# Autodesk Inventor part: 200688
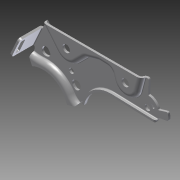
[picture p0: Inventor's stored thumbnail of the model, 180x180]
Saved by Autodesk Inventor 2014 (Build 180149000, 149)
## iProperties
Created: 2007-11
Part Number: 200688
Document SubType Name: Modeling
Designer: TH
Density: 7.85 g/cm^3
Mass: 313.071 g
Surface Area: 247.504 cm^2
Volume: 39.8817 cm^3
Material: Steel
Description: BACK SUPPORT PLATE
Appearance: Steel
Component Category: Lower Component
Author: TH
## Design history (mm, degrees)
sketch "Sketch2"
  geometry: L1 (-97.344, 50.026)-(-159.459, 48.117); L2 (-34.744, 9.425)-(-45.417, 12.32); L3 (-45.417, 12.32)-(-51.753, 20.365); L4 (-51.753, 20.365)-(-57.155, 19.109); L5 (4.666, 94.599)-(-151.434, 94.599); L6 (22.488, 55.351)-(4.666, 94.599); L7 (22.488, 55.351)-(17.318, 53.004); L8 (17.318, 53.004)-(19.939, 41.738); L9 (19.939, 41.738)-(15.518, 32.484); A1 r 36 centre (0, 0) between (15.518, 32.484) and (-34.744, 9.425); A2 r 40 centre (-96.115, 10.045) between (-57.155, 19.109) and (-97.344, 50.026); A3 r 24.073 centre (-160.199, 72.178) between (-151.434, 94.599) and (-159.459, 48.117); 1 further point
  constraints: 18 end point, 6 point on circle, 4 point on line, 3 centre point, 2 perpendicular, 2 tangent, 1 coincident
  dimensions: "d0" = 36 radius of A1; "d1" = 24.07258 radius of A3; "d2" = 40 radius of A2; "d3" = 94.59889 distance from line of point (0, 0) L5; "d4" = 160.19856 horizontal distance of point (0, 0) A3.centre; "d5" = 72.17844 vertical distance of point (0, 0) A3.centre; "d6" = 96.11496 horizontal distance of point (0, 0) A2.centre; "d7" = 10.04515 vertical distance of A2.centre point (0, 0); "d9" = 12.31989 vertical distance of point (0, 0) L2.end; "d10" = 20.36546 vertical distance of point (0, 0) L3.end; "d11" = 19.10873 vertical distance of point (0, 0) L4.end; "d12" = 45.41698 horizontal distance of point (0, 0) L2.end; "d15" = 19.9388 horizontal distance of point (0, 0) L8.end; "d16" = 17.31793 horizontal distance of point (0, 0) L7.end; "d17" = 55.35127 vertical distance of point (0, 0) L6.start; "d18" = 22.48806 horizontal distance of point (0, 0) L6.start; "d19" = 151.43427 horizontal distance of L5.end point (0, 0); "d137" = 41.73777 vertical distance of point (0, 0) L8.end
extrude "Extrusion1" new body sketch "Sketch2" distance "d20" = 3; taper "d21" = 0 deg
fillet "Fillet1" dims "d22" = 25
fillet "Fillet2" dims "d23" = 2
fillet "Fillet3" dims "d24" = 4
sketch "Sketch3"
  geometry: L1 (-4.666, -94.599)-(147.572, -94.599) reference; L2 (159.459, -48.117)-(97.344, -50.026) reference; L3 (45.417, -12.32)-(34.744, -9.425) reference; L4 (0, 23.92)-(0, -143.519) reference; L5 (228.741, 0)-(-64.359, 0) reference; L6 (0, -94.599)-(21.365, -68.832); L7 (99.254, -87.507)-(80, -88.099); L8 (80, -88.099)-(60, -82.674); L9 (60, -82.674)-(44.972, -67.708); L10 (99.254, -87.507)-(103.61, -74.101); L11 (139.559, -94.599)-(134.282, -74.904); A1 r 25 centre (147.572, -119.599) between (154.005, -95.441) and (147.572, -94.599) reference; A2 r 24.073 centre (160.199, -72.178) between (154.005, -95.441) and (159.459, -48.117) reference; A3 r 36 centre (0, 0) between (-15.518, -32.484) and (34.744, -9.425) reference; A4 r 16 centre (33.682, -79.045) between (21.365, -68.832) and (44.972, -67.708); A5 r 16 centre (118.827, -79.045) between (103.61, -74.101) and (134.282, -74.904)
  constraints: 12 end point, 4 point on circle, 4 tangent, 3 point on line, 2 centre point, 2 parallel
  dimensions: "d25" = 79.04516 vertical distance of A3.centre A4.centre; "d26" = 33.68204 horizontal distance of A3.centre A4.centre; "d28" = 79.04516 vertical distance of A3.centre A5.centre; "d29" = 32 diameter of A4; "d30" = 32 diameter of A5; "d33" = 60 distance from line of L8.end L4; "d34" = 80 distance from line of L4 L7.end; "d55" = 6.5 distance from line of L1 L7.end; "d170" = 118.82692 distance from line of A5.centre L4; "d171" = 15 deg angle of L11 L4; "d172" = 33 deg angle of L11 L10
extrude "Extrusion2" cut sketch "Sketch3" distance "d36" = 5; taper "d37" = 0 deg
fillet "Fillet4" dims "d38" = 10
sketch "Sketch4"
  geometry: L1 (53, -11.358)-(53, 0); L2 (53, 0)-(0, 0); L3 (53, 0)-(-52.769, 0); L4 (-52.769, 0)-(-27.664, -46.955); A1 r 36 centre (0, 0) between (-15.518, -32.484) and (34.744, -9.425) reference; A2 r 24 centre (57.131, -35) between (53, -11.358) and (36.666, -22.463); A3 r 47.5 centre (-7.912, -90.153) between (-3.759, -42.835) and (-27.664, -46.955); A4 r 43 centre (0, 0) between (-3.759, -42.835) and (36.666, -22.463)
  constraints: 8 end point, 6 point on circle, 3 centre point, 2 tangent, 1 coincident, 1 collinear, 1 horizontal, 1 perpendicular
  dimensions: "d42" = 24 radius of A2; "d43" = 95 diameter of A3; "d45" = 52.76853 distance of L3.end A1.centre; "d46" = 43 radius of A4; "d47" = 27.66425 horizontal distance of A1.centre L4.end; "d48" = 61.869 deg angle of L3 L4; "d138" = 35 distance from line of L3 A2.centre; "d139" = 53 distance from line of A1.centre L1
extrude "Extrusion3" cut sketch "Sketch4" distance "d51" = 5; taper "d52" = 0 deg
sketch "Sketch9"
  geometry: L1 (45.417, 12.32)-(51.753, 20.365) reference; L2 (34.744, 9.425)-(45.417, 12.32) reference; L3 (-19.939, 41.738)-(-15.518, 32.484) reference; L4 (-17.318, 53.004)-(-19.939, 41.738) reference; L5 (48.281, 15.956)-(46.38, 13.543); A1 r 24 centre (57.131, 35) between (36.666, 22.463) and (46.38, 13.543) reference; A2 r 47.5 centre (-7.912, 90.153) between (-19.398, 44.063) and (-3.759, 42.835) reference; A3 r 43 centre (0, 0) between (36.666, 22.463) and (-3.759, 42.835) reference; A4 r 36 centre (0, 0) between (34.744, 9.425) and (-15.518, 32.484) reference; A5 r 44.5 centre (-7.912, 90.153) between (-18.718, 46.985) and (-4.022, 45.824); A6 r 46 centre (0, 0) between (39.225, 24.03) and (-4.022, 45.824); A7 r 21 centre (57.131, 35) between (39.225, 24.03) and (48.281, 15.956)
  constraints: 6 point on circle, 3 centre point, 2 end point, 2 point on line, 1 collinear
  dimensions: "d73" = 3 radial gap between concentric circles of A3 A6; "d74" = 21 radius of A7; "d75" = 44.5 radius of A5
extrude "Extrusion7" join sketch "Sketch9" distance "d76" = 3; taper "d77" = 0 deg
sketch "Sketch10"
  geometry: L1 (48.281, 15.956)-(46.38, 13.543) reference; L2 (-19.398, 44.063)-(-18.718, 46.985) reference; L3 (34.744, 9.425)-(45.417, 12.32) reference; L4 (-19.939, 41.738)-(-15.518, 32.484) reference; L5 (46.38, 13.543)-(45.417, 12.32); L6 (-19.939, 41.738)-(-19.398, 44.063); A1 r 43 centre (0, 0) between (36.666, 22.463) and (-3.759, 42.835) reference; A2 r 24 centre (57.131, 35) between (36.666, 22.463) and (46.38, 13.543) reference; A3 r 21 centre (57.131, 35) between (39.225, 24.03) and (48.281, 15.956) reference; A4 r 46 centre (0, 0) between (39.225, 24.03) and (-4.022, 45.824) reference; A5 r 44.5 centre (-7.912, 90.153) between (-18.718, 46.985) and (-4.022, 45.824) reference; A6 r 47.5 centre (-7.912, 90.153) between (-19.398, 44.063) and (-3.759, 42.835) reference; A7 r 36 centre (0, 0) between (34.744, 9.425) and (-15.518, 32.484) reference
  constraints: 4 end point, 2 collinear
extrude "Extrusion8" join sketch "Sketch10" distance "d78" = 3; taper "d79" = 0 deg
fillet "Fillet11" dims "d80" = 4
fillet "Fillet12" dims "d81" = 7
fillet "Fillet13" dims "d82" = 1
sketch "Sketch11"
  geometry: L1 (50.18, 18.368)-(48.801, 16.617) reference; L2 (57.155, 19.109)-(54.229, 19.789) reference; L3 (159.459, 48.117)-(97.344, 50.026) reference; L4 (103.61, 74.101)-(101.427, 80.818) reference; L5 (92.224, 87.723)-(81.488, 88.053) reference; L6 (78.563, 87.709)-(62.559, 83.368) reference; L7 (58.121, 80.802)-(44.972, 67.708) reference; L8 (21.365, 68.832)-(0, 94.599) reference; L9 (-4.666, 94.599)-(0, 94.599) reference; L10 (-22.488, 55.351)-(-4.666, 94.599) reference; L11 (-18.81, 53.681)-(-22.488, 55.351) reference; L12 (-18.533, 47.782)-(-17.689, 51.407) reference; L13 (49.718, 18.733)-(48.628, 17.348); L14 (-17.827, 48.216)-(-17.116, 51.274); L15 (-18.567, 54.217)-(-21.708, 55.644); L16 (-21.708, 55.644)-(-4.287, 94.01); L17 (-4.287, 94.01)-(-0.277, 94.01); L18 (-0.277, 94.01)-(20.912, 68.456); L19 (45.388, 67.291)-(58.536, 80.385); L20 (62.714, 82.8)-(78.717, 87.141); L21 (81.47, 87.465)-(92.206, 87.135); L22 (100.867, 80.636)-(103.05, 73.919); L23 (134.851, 74.752)-(140.035, 94.101); L24 (159.551, 51.116)-(97.436, 53.025); L25 (159.551, 51.116)-(159.459, 48.117); A1 r 43.682 centre (-7.912, 90.153) between (-18.533, 47.782) and (-4.093, 46.638) reference; A2 r 46.818 centre (0, 0) between (39.922, 24.457) and (-4.093, 46.638) reference; A3 r 20.182 centre (57.131, 35) between (39.922, 24.457) and (48.801, 16.617) reference; A4 r 40 centre (96.115, 10.045) between (97.344, 50.026) and (57.155, 19.109) reference; A5 r 16 centre (118.827, 79.045) between (103.61, 74.101) and (134.282, 74.904) reference; A6 r 10 centre (91.917, 77.728) between (101.427, 80.818) and (92.224, 87.723) reference; A7 r 10 centre (81.181, 78.058) between (81.488, 88.053) and (78.563, 87.709) reference; A8 r 10 centre (65.177, 73.717) between (62.559, 83.368) and (58.121, 80.802) reference; A9 r 16 centre (33.682, 79.045) between (21.365, 68.832) and (44.972, 67.708) reference; A10 r 2 centre (-19.637, 51.86) between (-17.689, 51.407) and (-18.81, 53.681) reference; A11 r 19.593 centre (57.131, 35) between (40.424, 24.765) and (48.628, 17.348); A12 r 47.407 centre (0, 0) between (40.424, 24.765) and (-4.145, 47.225); A13 r 43.093 centre (-7.912, 90.153) between (-17.827, 48.216) and (-4.145, 47.225); A14 r 2.589 centre (-19.637, 51.86) between (-17.116, 51.274) and (-18.567, 54.217); A15 r 16.589 centre (33.682, 79.045) between (20.912, 68.456) and (45.388, 67.291); A16 r 9.411 centre (65.177, 73.717) between (62.714, 82.8) and (58.536, 80.385); A17 r 9.411 centre (81.181, 78.058) between (81.47, 87.465) and (78.717, 87.141); A18 r 9.411 centre (91.917, 77.728) between (100.867, 80.636) and (92.206, 87.135); A19 r 16.589 centre (118.827, 79.045) between (103.05, 73.919) and (134.851, 74.752); A20 r 43 centre (96.115, 10.045) between (97.436, 53.025) and (54.233, 19.789); 2 further points; 1 other entity
  constraints: 26 end point, 20 point on circle, 10 centre point, 1 perpendicular, 1 point on line, 20 other
  dimensions: "d83" = 3 distance between parallel lines of L3 L24; "d84" = 43 radius of A20
extrude "Extrusion9" join sketch "Sketch11" distance "d85" = 4; taper "d86" = 0 deg
sketch "Sketch12"
  geometry: L1 (103.61, 74.101)-(101.427, 80.818) reference; L2 (92.224, 87.723)-(81.488, 88.053) reference; L3 (78.563, 87.709)-(62.559, 83.368) reference; L4 (58.121, 80.802)-(44.972, 67.708) reference; L5 (21.365, 68.832)-(0, 94.599) reference; L6 (-1.41, 91.599)-(19.056, 66.917); L7 (47.089, 65.582)-(60.238, 78.677); L8 (63.345, 80.473)-(79.348, 84.814); L9 (81.396, 85.055)-(92.132, 84.725); L10 (98.574, 79.891)-(100.757, 73.174); L11 (137.18, 74.128)-(142.665, 94.599); L12 (-1.41, 91.599)-(0, 94.599); L13 (139.559, 94.599)-(147.572, 94.599) reference; A1 r 16 centre (118.827, 79.045) between (103.61, 74.101) and (134.282, 74.904) reference; A2 r 10 centre (91.917, 77.728) between (101.427, 80.818) and (92.224, 87.723) reference; A3 r 10 centre (81.181, 78.058) between (81.488, 88.053) and (78.563, 87.709) reference; A4 r 10 centre (65.177, 73.717) between (62.559, 83.368) and (58.121, 80.802) reference; A5 r 16 centre (33.682, 79.045) between (21.365, 68.832) and (44.972, 67.708) reference; A6 r 19 centre (33.682, 79.045) between (19.056, 66.917) and (47.089, 65.582); A7 r 7 centre (65.177, 73.717) between (63.345, 80.473) and (60.238, 78.677); A8 r 7 centre (81.181, 78.058) between (81.396, 85.055) and (79.348, 84.814); A9 r 7 centre (91.917, 77.728) between (98.574, 79.891) and (92.132, 84.725); A10 r 19 centre (118.827, 79.045) between (100.757, 73.174) and (137.18, 74.128); A11 r 24.073 centre (160.199, 72.178) between (159.459, 48.117) and (154.005, 95.441) reference; 2 further points; 1 other entity
  constraints: 14 end point, 11 point on circle, 5 centre point, 2 point on line, 10 other
  dimensions: "d87" = 3 distance between parallel lines of L2 L9; "d88" = 3 dimension on L11
extrude "Extrusion10" join sketch "Sketch12" distance "d89" = 3; taper "d90" = 0 deg
sketch "Sketch13"
  geometry: L1 (101.427, 80.818)-(103.61, 74.101) reference; L2 (81.488, 88.053)-(92.224, 87.723) reference; L3 (62.559, 83.368)-(78.563, 87.709) reference; L4 (44.972, 67.708)-(58.121, 80.802) reference; L5 (0, 94.599)-(21.365, 68.832) reference; L6 (-1.41, 91.599)-(0, 94.599) reference; L7 (19.056, 66.917)-(-1.41, 91.599) reference; L8 (60.238, 78.677)-(47.089, 65.582) reference; L9 (79.348, 84.814)-(63.345, 80.473) reference; L10 (92.132, 84.725)-(81.396, 85.055) reference; L11 (100.757, 73.174)-(98.574, 79.891) reference; L12 (142.665, 94.599)-(137.18, 74.128) reference; L13 (0, 94.599)-(0, 94.599); L14 (0, 94.599)-(142.665, 94.599); A1 r 16 centre (118.827, 79.045) between (103.61, 74.101) and (134.282, 74.904) reference; A2 r 10 centre (91.917, 77.728) between (101.427, 80.818) and (92.224, 87.723) reference; A3 r 10 centre (81.181, 78.058) between (81.488, 88.053) and (78.563, 87.709) reference; A4 r 10 centre (65.177, 73.717) between (62.559, 83.368) and (58.121, 80.802) reference; A5 r 16 centre (33.682, 79.045) between (21.365, 68.832) and (44.972, 67.708) reference; A6 r 19 centre (33.682, 79.045) between (19.056, 66.917) and (47.089, 65.582) reference; A7 r 7 centre (65.177, 73.717) between (63.345, 80.473) and (60.238, 78.677) reference; A8 r 7 centre (81.181, 78.058) between (81.396, 85.055) and (79.348, 84.814) reference; A9 r 7 centre (91.917, 77.728) between (98.574, 79.891) and (92.132, 84.725) reference; A10 r 19 centre (118.827, 79.045) between (100.757, 73.174) and (137.18, 74.128) reference; A11 r 37.952 centre (160.199, 72.178) between (123.216, 63.659) and (124.004, 60.764); 2 further points
  constraints: 4 end point, 4 point on circle, 1 centre point, 1 collinear, 1 horizontal, 1 point on line
extrude "Extrusion11" join sketch "Sketch13" distance "d92" = 3; taper "d93" = 0 deg
fillet "Fillet14" dims "d94" = 4
fillet "Fillet15" dims "d95" = 7, "d96" = 1
fillet "Fillet16" dims "d97" = 4
fillet "Fillet18" dims "d99" = 2
sketch "Sketch14"
  geometry: L1 (159.459, -48.117)-(97.344, -50.026) reference; L2 (159.459, -48.117)-(159.459, -53.12); L3 (159.459, -53.12)-(178.13, -56.117); A1 r 24.073 centre (160.199, -72.178) between (154.005, -95.441) and (159.459, -48.117) reference; 2 further points
  constraints: 4 end point, 1 point on circle
  dimensions: "d100" = 0 horizontal distance of L1.start L2.end; "d101" = 5 distance from line of L2.end L1; "d102" = 8 vertical distance of L1.start L3.end
extrude "Extrusion12" cut sketch "Sketch14" stored distance "d103" = 3; taper "d104" = 0 deg
fillet "Fillet19" dims "d105" = 4
fillet "Fillet20" dims "d106" = 1
fillet "Fillet21" dims "d107" = 15
fillet "Fillet22" dims "d108" = 5
fillet "Fillet23" dims "d109" = 2.5
sketch "Sketch15"
  geometry: L1 (0, 0)-(30, 0); L2 (30, 0)-(30, -32); L3 (30, -32)-(0, -32); L4 (0, -32)-(0, 0); L5 (4.5, -28)-(25.5, -28); L6 (25.5, -28)-(25.5, -22); L7 (25.5, -22)-(4.5, -22); L8 (4.5, -22)-(4.5, -28); L9 (30, 0)-(40, 0); L10 (40, 0)-(40, -2); L11 (40, -2)-(30, -2); L12 (30, -2)-(30, 0); 1 further point
  constraints: 24 end point, 6 parallel, 3 horizontal, 3 perpendicular
  dimensions: "d110" = 32 distance of L3.end L1.start; "d111" = 30 distance of L2.end L3.end; "d112" = 4 distance between parallel lines of L3 L5; "d113" = 6 distance of L7.end L5.start; "d114" = 4.5 distance between parallel lines of L4 L8; "d115" = 4.5 distance between parallel lines of L2 L6; "d120" = 2 distance of L9.end L10.end; "d121" = 10 distance of L10.end L11.end
extrude "Extrusion13" join sketch "Sketch15" distance "d116" = 3; taper "d117" = 0 deg
fillet "Fillet25" dims "d119" = 1
sketch "Sketch16"
  geometry: L1 (-10.084, 82.667)-(-4.666, 94.599) reference; L2 (-10.084, 82.667)-(-6.442, 81.013) reference; L3 (-6.442, 81.013)-(0.588, 96.495); L4 (0.588, 96.495)-(-3.054, 98.149); L5 (-6.442, 81.013)-(-10.084, 82.667); L6 (-10.084, 82.667)-(-3.054, 98.149)
  constraints: 8 end point, 2 perpendicular, 1 collinear
extrude "Extrusion14" cut sketch "Sketch16" stored distance "d122" = 10; taper "d123" = 0 deg
fillet "Fillet26" dims "d124" = 4
fillet "Fillet27" dims "d125" = 4
fillet "Fillet28" dims "d126" = 1
workplane "Work Plane2"
  workaxis "Work Axis1"
sketch "Sketch17"
  geometry: A1 r 12 centre (118.827, -79.045) between (130.418, -75.939) and (107.414, -75.337) reference; A2 r 12 centre (33.682, -79.045) between (42.15, -70.542) and (24.445, -71.386) reference; 3 further points
  constraints: 2 coincident
hole "Hole1" sketch "Sketch17" at (33.682, -79.045), (118.827, -79.045) diameter "d128" = 10.5; stored, may be unused: countersink angle "d132" = 90 deg, drill point angle "d134" = 118 deg; dims "d129" = 6, "d130" = 4, "d131" = 2, "d133" = 8
sketch "Sketch18"
  geometry: L1 (-18.81, -53.681)-(-18.846, -53.697) reference; L2 (-2.133, -49.176)-(0.108, -49.395); L3 (-6.241, -58.27)-(-7.172, -56.22); L4 (2.378, -59.112)-(3.688, -57.281); L5 (37.12, -32.588)-(38.43, -30.757); L6 (47.05, -31.598)-(47.981, -33.649); L7 (42.942, -40.692)-(40.701, -40.473); A1 r 5 centre (42.497, -33.666) between (47.05, -31.598) and (38.43, -30.757) reference; A2 r 5 centre (43.428, -35.716) between (42.942, -40.692) and (47.981, -33.649) reference; A3 r 5 centre (41.187, -35.497) between (37.12, -32.588) and (40.701, -40.473) reference; A4 r 5 centre (-0.378, -54.371) between (3.688, -57.281) and (0.108, -49.395) reference; A5 r 5 centre (-2.619, -54.153) between (-2.133, -49.176) and (-7.172, -56.22) reference; A6 r 5 centre (-1.688, -56.203) between (-6.241, -58.27) and (2.378, -59.112) reference; 1 further point
  constraints: 12 end point, 12 point on circle, 10 tangent, 6 centre point, 3 parallel, 1 perpendicular, 24 other
extrude "Extrusion15" cut sketch "Sketch18" stored distance "d135" = 10; taper "d136" = 0 deg
sketch "Sketch19"
  geometry: C1 r 3.55 at (35.126, -48.872); 2 further points
  constraints: 1 centre point, 1 coincident
  dimensions: "d140" = 7.1 diameter of C1; "d145" = 35.12571 horizontal distance of point (0, 0) point (35.126, -48.872); "d146" = 48.87222 vertical distance of point (0, 0) point (35.126, -48.872)
extrude "Extrusion16" cut sketch "Sketch19" stored distance "d143" = 10; taper "d144" = 0 deg
sketch "Sketch21"
  geometry: L1 (160.314, -62.469)-(184.137, -69.643); L2 (145.781, -73.865)-(146.773, -94.599); L3 (0, 20.786)-(0, -124.717) reference; L4 (234.84, 0)-(-65.376, 0) reference; L5 (143.437, -94.599)-(147.572, -94.599) reference; A1 r 24.073 centre (160.199, -72.178) between (154.005, -95.441) and (183.456, -65.968) reference; A2 r 16 centre (144.984, -57.885) between (145.781, -73.865) and (160.314, -62.469); A3 r 15 centre (168.964, -69.838) between (183.456, -65.968) and (171.342, -55.027) reference; A4 r 25 centre (147.572, -119.599) between (154.005, -95.441) and (147.572, -94.599) reference; 4 further points
  constraints: 4 end point, 4 point on circle, 2 coincident, 2 point on line, 1 centre point
  dimensions: "d157" = 16 radius of A2; "d158" = 16.7603 deg angle of L1 L4; "d159" = 2.73967 deg angle of L3 L2; "d160" = 0.79648 horizontal distance of point (144.984, -57.885) L2.start; "d161" = 4.58349 vertical distance of point (144.984, -57.885) L1.start; "d182" = 144.98439 distance from line of L3 point (144.984, -57.885); "d183" = 57.88514 distance from line of point (144.984, -57.885) L4
extrude "Extrusion17" cut sketch "Sketch21" stored distance "d162" = 10; taper "d163" = 0 deg
fillet "Fillet29" dims "d164" = 1
chamfer "Chamfer1" distance "d165" = 1; stored, may be unused: second distance "d166" = 2, angle "d167" = 45 deg
sketch "Sketch22"
  geometry: 2 further points
  dimensions: "d173" = 144.98439 horizontal distance of point (0, 0) point (144.984, -57.885); "d174" = 57.88514 vertical distance of point (144.984, -57.885) point (0, 0)
hole "Hole3" sketch "Sketch22" at (144.984, -57.885) diameter "d175" = 8; stored, may be unused: countersink angle "d179" = 90 deg, drill point angle "d181" = 118 deg; dims "d176" = 6, "d177" = 4, "d178" = 2, "d180" = 8
sketch "Sketch23"
  geometry: L1 (184.011, -68.652)-(183.18, -69.355) reference; L2 (161.245, -62.749)-(183.18, -69.355) reference; C1 r 0.032 at (144.984, -57.885); A1 r 24.073 centre (160.199, -72.178) between (184.011, -68.652) and (183.456, -65.968) reference; A2 r 15 centre (168.964, -69.838) between (183.456, -65.968) and (171.342, -55.027) reference; A3 r 16 centre (144.984, -57.885) between (146.718, -73.791) and (160.017, -63.364) reference; A4 r 30 centre (144.984, -57.885) between (173.719, -66.506) and (174.93, -56.075); 1 further point
  constraints: 3 point on circle, 2 centre point, 2 coincident, 1 point on line, 1 tangent
  dimensions: "d185" = 30 radius of A4
extrude "Extrusion18" cut sketch "Sketch23" stored distance "d186" = 10; taper "d187" = 0 deg
fillet "Fillet30" dims "d188" = 2
sketch "Sketch24"
  geometry: L1 (150.741, -63.539)-(151.949, -61.351); L2 (154.575, -62.801)-(153.367, -64.99); A1 r 1.5 centre (153.262, -62.076) between (154.575, -62.801) and (151.949, -61.351); A2 r 1.5 centre (152.054, -64.264) between (150.741, -63.539) and (153.367, -64.99)
  constraints: 4 end point, 4 point on circle, 4 tangent, 2 centre point, 1 parallel
  dimensions: "d189" = 3 distance between parallel lines of L2 L1; "d190" = 2.5 distance of A2.centre A1.centre
extrude "Extrusion19" cut sketch "Sketch24" stored distance "d191" = 10; taper "d192" = 0 deg
body "Solid1"
other parameters: "d41" = 83, "d127" = 90 deg, "d156" = 16
